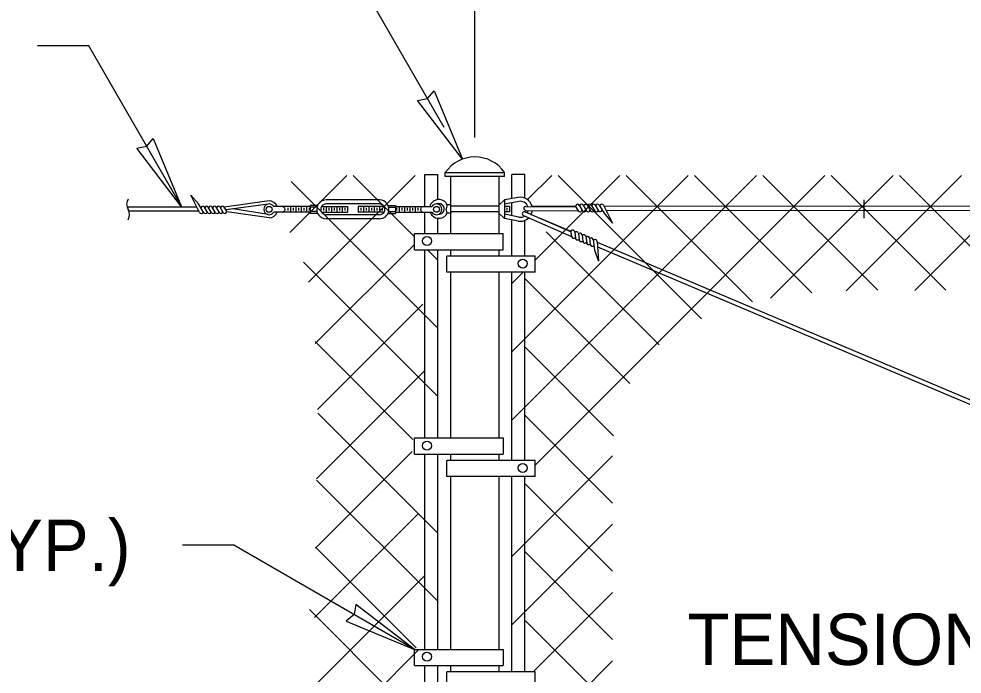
# Model space of a CAD drawing. Extents: x 99862 to 104211, y 98939 to 105076.
# Drawn here: x 100145.4 to 100439.3, y 101445.9 to 101650.2 of the extents above; entities that cross this region are included whole.
import ezdxf

# ---------------------------------------------------------------- set-up
doc = ezdxf.new("R2010")
doc.units = 0
for name, color, linetype in [('Level 15', 7, 'Continuous'), ('Level 2', 7, 'Continuous'), ('Level 20', 7, 'Continuous'), ('Level 4', 7, 'Continuous'), ('Level 7', 7, 'Continuous')]:
    doc.layers.add(name, color=color, linetype=linetype)

msp = doc.modelspace()

# ---------------------------------------------------------------- linework, layer by layer
at = {"layer": 'Level 15'}
for p, q in [((100287.45, 101613.16), (100287.45, 101829.45)), ((100277.92, 101616.32), (100233.56, 101693.15)), ((100167.16, 101641.76), (100151.16, 101641.76)), ((100196.2, 101591.48), (100167.16, 101641.76)), ((100212.4, 101486.13), (100196.4, 101486.13)), ((100268.69, 101453.63), (100212.4, 101486.13))]:
    msp.add_line(p, q, dxfattribs=at)
for points in [[(100283.63, 101606.43), (100269.63, 101624.71), (100272.74, 101625.29), (100274.8, 101627.69)], [(100283.63, 101606.43), (100269.63, 101624.71), (100272.74, 101625.29), (100274.8, 101627.69)], [(100196.11, 101591.62), (100182.11, 101609.9), (100185.23, 101610.48), (100187.28, 101612.89)], [(100196.11, 101591.62), (100182.11, 101609.9), (100185.23, 101610.48), (100187.28, 101612.89)], [(100268.69, 101453.63), (100250.41, 101467.63), (100249.83, 101464.52), (100247.43, 101462.46)]]:
    msp.add_lwpolyline(points, close=True, dxfattribs=at)
at = {"layer": 'Level 2'}
for p, q in [((100201.39, 101592.51), (100198.99, 101595.18)), ((100201.72, 101589.81), (100198.99, 101595.18)), ((100300.99, 101594.5), (100296.67, 101593.73)), ((100203.02, 101589.74), (100201.39, 101592.51)), ((100205.46, 101589.72), (100204.38, 101591.52)), ((100223.34, 101593.42), (100209.37, 101591.43)), ((100223.13, 101592.44), (100209.93, 101590.63)), ((100228.36, 101591.63), (100224.81, 101591.63)), ((100236.13, 101591.63), (100228.36, 101591.63)), ((100230.03, 101591.63), (100230.03, 101589.96)), ((100231.69, 101591.63), (100231.69, 101589.96)), ((100233.36, 101591.63), (100233.36, 101589.96)), ((100235.03, 101591.63), (100235.03, 101589.96)), ((100236.13, 101592.04), (100236.13, 101589.54)), ((100238.49, 101592.04), (100236.13, 101592.04)), ((100239.68, 101591.63), (100247.79, 101591.63)), ((100241.12, 101591.63), (100241.12, 101589.96)), ((100257.79, 101593.71), (100241.13, 101593.71)), ((100257.79, 101592.46), (100241.13, 101592.46)), ((100242.79, 101591.63), (100242.79, 101589.96)), ((100244.45, 101591.63), (100244.45, 101589.96)), ((100246.12, 101591.63), (100246.12, 101589.96)), ((100247.79, 101591.63), (100247.79, 101589.96)), ((100259.22, 101591.63), (100251.12, 101591.63)), ((100251.12, 101591.63), (100251.12, 101589.96)), ((100252.78, 101591.63), (100252.78, 101589.96)), ((100254.45, 101591.63), (100254.45, 101589.96)), ((100256.12, 101591.63), (100256.12, 101589.96)), ((100257.78, 101591.63), (100257.78, 101589.96)), ((100260.42, 101592.04), (100262.79, 101592.04)), ((100262.79, 101592.04), (100262.79, 101589.54)), ((100262.79, 101591.63), (100270.54, 101591.63)), ((100263.88, 101591.63), (100263.88, 101589.96)), ((100265.54, 101591.63), (100265.54, 101589.96)), ((100267.21, 101591.63), (100267.21, 101589.96)), ((100268.88, 101591.63), (100268.88, 101589.96)), ((100270.52, 101591.63), (100274.08, 101591.63)), ((100278.9, 101592.15), (100278.51, 101590.9)), ((100295.03, 101591.73), (100279.88, 101591.73)), ((100296.67, 101593.73), (100294.99, 101592.05)), ((100294.99, 101591.65), (100294.99, 101589.98)), ((100296.67, 101593.73), (100296.67, 101587.89)), ((100301.17, 101593.27), (100296.67, 101592.39)), ((100298.32, 101591.65), (100296.67, 101591.65)), ((100298.32, 101591.65), (100298.32, 101589.98)), ((100303.36, 101591.71), (100318.79, 101591.62)), ((100305.29, 101591.73), (100309.12, 101591.75)), ((100308.63, 101591.74), (100318.86, 101591.79)), ((100320.01, 101592.06), (100321.02, 101590.34)), ((100321.24, 101592.09), (100322.28, 101590.32)), ((100322.48, 101592.12), (100323.54, 101590.35)), ((100323.71, 101592.14), (100324.84, 101590.28)), ((100324.97, 101592.14), (100326.03, 101590.37)), ((100326.24, 101592.12), (100327.93, 101589.26)), ((100327.59, 101592.05), (100330.42, 101586.51)), ((100327.74, 101591.76), (100958.96, 101592.39)), ((100200.87, 101591.48), (100179.1, 101591.48)), ((100201.53, 101590.18), (100179.67, 101590.18)), ((100204.25, 101589.72), (100203.23, 101591.43)), ((100206.66, 101589.74), (100205.64, 101591.45)), ((100207.86, 101589.76), (100206.85, 101591.47)), ((100209.05, 101589.78), (100208.08, 101591.45)), ((100210.02, 101590.5), (100209.37, 101591.43)), ((100223.38, 101588.17), (100210.17, 101590.04)), ((100223.18, 101589.14), (100212.07, 101590.93)), ((100228.36, 101589.96), (100224.81, 101589.96)), ((100236.13, 101589.96), (100228.36, 101589.96)), ((100229.19, 101591.21), (100229.19, 101590.38)), ((100230.86, 101591.21), (100230.86, 101590.38)), ((100232.53, 101591.21), (100232.53, 101590.38)), ((100234.19, 101591.21), (100234.19, 101590.38)), ((100235.86, 101591.21), (100235.86, 101590.38)), ((100238.49, 101589.54), (100236.13, 101589.54)), ((100239.68, 101589.96), (100247.79, 101589.96)), ((100240.29, 101591.21), (100240.29, 101590.38)), ((100257.79, 101589.13), (100241.11, 101589.13)), ((100241.95, 101591.21), (100241.95, 101590.38)), ((100243.62, 101591.21), (100243.62, 101590.38)), ((100245.29, 101591.21), (100245.29, 101590.38)), ((100246.95, 101591.21), (100246.95, 101590.38)), ((100259.22, 101589.96), (100251.12, 101589.96)), ((100251.95, 101591.21), (100251.95, 101590.38)), ((100253.62, 101591.21), (100253.62, 101590.38)), ((100255.28, 101591.21), (100255.28, 101590.38)), ((100256.95, 101591.21), (100256.95, 101590.38)), ((100258.62, 101591.21), (100258.62, 101590.38)), ((100260.42, 101589.54), (100262.79, 101589.54)), ((100262.79, 101589.96), (100270.54, 101589.96)), ((100263.04, 101591.21), (100263.04, 101590.38)), ((100264.71, 101591.21), (100264.71, 101590.38)), ((100266.38, 101591.21), (100266.38, 101590.38)), ((100268.04, 101591.21), (100268.04, 101590.38)), ((100269.71, 101591.21), (100269.71, 101590.38)), ((100270.52, 101589.96), (100274.08, 101589.96)), ((100278.9, 101589.65), (100278.51, 101590.9)), ((100295.01, 101590.06), (100279.96, 101590.06)), ((100294.99, 101590.81), (100294.99, 101589.98)), ((100296.67, 101587.89), (100294.99, 101589.58)), ((100298.32, 101589.98), (100296.67, 101589.98)), ((100301.17, 101588.36), (100296.67, 101589.25)), ((100297.49, 101591.23), (100297.49, 101590.4)), ((100302.64, 101588.83), (100317.62, 101582.34)), ((100303.13, 101589.98), (100317.29, 101583.84)), ((100303.36, 101590.46), (100319.69, 101590.36)), ((100305.03, 101589.19), (100308.44, 101587.75)), ((100319.01, 101591.32), (100319.69, 101590.36)), ((100327.93, 101589.26), (100330.42, 101586.51)), ((100328.4, 101590.46), (100958.31, 101591.09)), ((100257.79, 101587.88), (100241.11, 101587.88)), ((100300.99, 101587.12), (100296.67, 101587.89)), ((100307.99, 101587.94), (100317.41, 101583.98)), ((100317.37, 101583.48), (100317.62, 101582.34)), ((100318.58, 101583.77), (100318.83, 101581.79)), ((100319.73, 101583.31), (100319.99, 101581.28)), ((100320.87, 101582.85), (100321.15, 101580.81)), ((100322.02, 101582.39), (100322.32, 101580.24)), ((100323.17, 101581.89), (100323.46, 101579.85)), ((100324.33, 101581.38), (100324.77, 101578.09)), ((100325.55, 101580.79), (100325.98, 101574.59)), ((100325.56, 101580.53), (100643.48, 101446.13)), ((100324.77, 101578.09), (100325.98, 101574.59)), ((100325.66, 101579.07), (100641.81, 101445.42))]:
    msp.add_line(p, q, dxfattribs=at)
for points in [[(100279.96, 101591.73), (100279.96, 101592.15), (100278.9, 101592.15)], [(100294.99, 101591.65), (100294.99, 101592.05)], [(100238.29, 101591.48), (100236.13, 101591.48)], [(100238.29, 101590.11), (100236.13, 101590.11)], [(100260.62, 101591.48), (100262.79, 101591.48)], [(100260.62, 101590.11), (100262.79, 101590.11)], [(100279.96, 101590.06), (100279.96, 101589.65), (100278.9, 101589.65)], [(100294.99, 101589.98), (100294.99, 101589.58)]]:
    msp.add_lwpolyline(points, dxfattribs=at)
for centre in [(100223.36, 101590.79), (100275.52, 101590.79)]:
    msp.add_circle(centre, 0.916, dxfattribs=at)
for centre, radius, start, end in [((100301.65, 101590.81), 3.75, 13.7093, 100.1113), ((100182.18, 101592.37), 3.2, 150, 210), ((100202.71, 101591.12), 0.605, 30.782, 165.4463), ((100203.91, 101591.14), 0.605, 23.3152, 166.8445), ((100205.12, 101591.14), 0.605, 30.6723, 167.4674), ((100206.35, 101591.15), 0.605, 27.9114, 168.3683), ((100207.56, 101591.15), 0.605, 30.168, 167.2951), ((100208.83, 101591.15), 0.605, 26.9228, 174.8711), ((100223.36, 101590.79), 1.67, 30, 330), ((100223.36, 101590.79), 2.63, 18.6792, 90.4624), ((100227.51, 101590.79), 0.833, 270, 90), ((100241.13, 101590.79), 2.92, 89.9981, 166.4719), ((100241.13, 101590.79), 1.67, 89.9982, 210.0013), ((100257.79, 101590.79), 2.92, 342.3838, 90.0019), ((100257.79, 101590.79), 1.67, 330, 90.0018), ((100271.38, 101590.79), 0.833, 90, 270), ((100276.26, 101590.9), 2.92, 25.3769, 164.6604), ((100275.52, 101590.79), 1.67, 210, 150), ((100276.26, 101590.9), 1.67, 318.0518, 110.808), ((100301.65, 101590.81), 2.5, 21.0207, 101.0207), ((100303.36, 101591.09), 0.625, 90.3003, 270.3003), ((100319.48, 101591.73), 0.625, 28.456, 221.3397), ((100320.73, 101591.74), 0.625, 34.1636, 167.3928), ((100321.98, 101591.74), 0.625, 36.9231, 167.4504), ((100323.23, 101591.75), 0.625, 38.8294, 167.5824), ((100324.48, 101591.76), 0.625, 37.6123, 167.7021), ((100325.73, 101591.76), 0.625, 35.1739, 167.6232), ((100327.03, 101591.77), 0.625, 27.058, 173.8967), ((100176.64, 101589.17), 3.2, 330, 30), ((100202.26, 101590.09), 0.605, 206.9027, 353.7414), ((100203.52, 101590.09), 0.605, 205.8452, 347.468), ((100204.73, 101590.09), 0.605, 204.107, 347.5468), ((100205.94, 101590.09), 0.605, 203.3152, 347.4271), ((100207.15, 101590.1), 0.605, 204.5768, 347.2951), ((100208.36, 101590.1), 0.605, 206.6324, 347.2375), ((100209.57, 101590.1), 0.605, 208.3007, 41.1845), ((100223.36, 101590.79), 2.63, 270.4624, 341.4954), ((100241.13, 101590.79), 2.92, 166.4719, 270), ((100241.13, 101590.79), 1.67, 210.0013, 270), ((100257.79, 101590.79), 2.92, 270, 346.4753), ((100257.79, 101590.79), 1.67, 270, 330), ((100276.26, 101590.9), 2.92, 198.7095, 220.0117), ((100276.26, 101590.9), 2.92, 220.0117, 334.6231), ((100276.26, 101590.9), 1.67, 264.9526, 318.0518), ((100301.65, 101590.81), 2.5, 258.8638, 301.8406), ((100302.88, 101589.41), 0.625, 67.2, 247.2), ((100301.65, 101590.81), 2.5, 332.5747, 351.8513), ((100301.65, 101590.81), 3.75, 333.9004, 354.4593), ((100320.24, 101590.65), 0.625, 207.0781, 355.0264), ((100321.56, 101590.65), 0.625, 210.3232, 347.4504), ((100322.81, 101590.66), 0.625, 208.0667, 348.5236), ((100324.08, 101590.67), 0.625, 210.8276, 347.6226), ((100325.32, 101590.67), 0.625, 218.8294, 346.9998), ((100326.57, 101590.69), 0.625, 210.9373, 345.6016), ((100301.65, 101590.81), 3.75, 259.8887, 314.2398), ((100317.96, 101583.67), 0.625, 5.3557, 198.2394), ((100319.11, 101583.19), 0.625, 11.0633, 144.2925), ((100320.26, 101582.7), 0.625, 13.8228, 144.3501), ((100321.42, 101582.22), 0.625, 15.7291, 144.4821), ((100318.24, 101582.38), 0.625, 183.9778, 331.9261), ((100319.45, 101581.87), 0.625, 187.2229, 324.3501), ((100320.6, 101581.38), 0.625, 184.9664, 325.4233), ((100321.77, 101580.89), 0.625, 187.7273, 324.5224), ((100322.57, 101581.74), 0.625, 14.5121, 144.6018), ((100322.92, 101580.41), 0.625, 195.7291, 323.8995), ((100323.72, 101581.25), 0.625, 12.0736, 144.523), ((100324.08, 101579.94), 0.625, 187.837, 322.5013), ((100324.92, 101580.75), 0.625, 3.9577, 150.7964)]:
    msp.add_arc(centre, radius, start, end, dxfattribs=at)
at = {"layer": 'Level 4'}
for p, q in [((100229.84, 101583.59), (100247.61, 101601.36)), ((100235.6, 101568.08), (100268.89, 101601.36)), ((100268.69, 101582.26), (100249.58, 101601.36)), ((100299.03, 101546.41), (100353.98, 101601.36)), ((100299.03, 101525.12), (100375.26, 101601.36)), ((100303.88, 101593.83), (100311.42, 101601.36)), ((100306.25, 101511.07), (100396.54, 101601.36)), ((100306.3, 101574.97), (100332.7, 101601.36)), ((100358.1, 101556.68), (100313.43, 101601.36)), ((100374.03, 101561.97), (100334.64, 101601.36)), ((100392.45, 101564.82), (100355.91, 101601.36)), ((100413, 101565.55), (100377.19, 101601.36)), ((100379.61, 101563.15), (100417.83, 101601.36)), ((100434.26, 101565.59), (100398.49, 101601.36)), ((100403.15, 101565.41), (100439.1, 101601.36)), ((100454.88, 101566.23), (100419.75, 101601.36)), ((100424.55, 101565.53), (100460.39, 101601.36)), ((100275.96, 101553.71), (100230.2, 101599.47)), ((100408.77, 101588.05), (100408.77, 101593.75)), ((100344.96, 101548.54), (100309.72, 101583.79)), ((100237.75, 101548.93), (100268.69, 101579.87)), ((100275.96, 101574.99), (100272.75, 101578.2)), ((100275.96, 101532.44), (100234.07, 101574.33)), ((100299.03, 101567.69), (100302.51, 101571.18)), ((100335.77, 101536.46), (100303.03, 101569.2)), ((100238.44, 101528.39), (100271.29, 101561.24)), ((100268.19, 101519.03), (100237.69, 101549.56)), ((100330.73, 101520.21), (100302.92, 101548.03)), ((100238.12, 101506.78), (100271.66, 101540.32)), ((100275.96, 101489.86), (100238.54, 101527.28)), ((100330.41, 101499.26), (100302.87, 101526.8)), ((100237.8, 101485.18), (100267.91, 101515.29)), ((100299.03, 101482.57), (100330.41, 101513.94)), ((100276.01, 101468.54), (100238.12, 101506.43)), ((100330.41, 101477.99), (100303.09, 101505.3)), ((100237.48, 101463.57), (100269.94, 101496.03)), ((100299.13, 101461.39), (100330.41, 101492.67)), ((100269.16, 101454.11), (100237.81, 101485.46)), ((100330.41, 101456.73), (100303.07, 101484.1)), ((100236.47, 101441.29), (100271.77, 101476.59)), ((100305.96, 101446.96), (100330.41, 101471.4)), ((100275.96, 101426.04), (100235.97, 101466.03)), ((100330.41, 101435.42), (100303.25, 101462.57)), ((100236.84, 101420.38), (100269.94, 101453.48)), ((100299.03, 101418.73), (100330.41, 101450.1))]:
    msp.add_line(p, q, dxfattribs=at)
at = {"layer": 'Level 7'}
for p, q in [((100271.94, 101592.37), (100271.94, 101601.64)), ((100271.94, 101601.64), (100275.96, 101601.64)), ((100275.96, 101593.8), (100275.96, 101601.64)), ((100278.27, 101602.27), (100296.72, 101602.27)), ((100278.27, 101601.02), (100278.27, 101602.27)), ((100296.72, 101601.02), (100278.27, 101601.02)), ((100279.97, 101583.21), (100279.97, 101601.02)), ((100295.02, 101583.21), (100295.02, 101601.02)), ((100296.72, 101601.02), (100296.72, 101602.27)), ((100299.03, 101594.15), (100299.03, 101601.64)), ((100303.05, 101601.64), (100299.03, 101601.64)), ((100303.05, 101594.29), (100303.05, 101601.64)), ((100271.94, 101591.63), (100271.94, 101592.37)), ((100299.03, 101588.78), (100299.03, 101592.85)), ((100271.94, 101583.21), (100271.94, 101589.96)), ((100275.96, 101583.21), (100275.96, 101588)), ((100299.03, 101576.19), (100299.03, 101587.47)), ((100303.05, 101576.19), (100303.05, 101587.34)), ((100268.69, 101583.21), (100296.27, 101583.21)), ((100268.69, 101578.2), (100268.69, 101583.21)), ((100296.27, 101578.2), (100296.27, 101583.21)), ((100268.69, 101578.2), (100296.27, 101578.2)), ((100271.94, 101519.53), (100271.94, 101578.2)), ((100275.96, 101519.53), (100275.96, 101578.2)), ((100279.97, 101576.19), (100279.97, 101578.2)), ((100295.02, 101576.19), (100295.02, 101578.2)), ((100306.3, 101576.19), (100278.72, 101576.19)), ((100278.72, 101571.18), (100278.72, 101576.19)), ((100306.3, 101571.18), (100306.3, 101576.19)), ((100306.3, 101571.18), (100278.72, 101571.18)), ((100279.97, 101519.53), (100279.97, 101571.18)), ((100295.02, 101519.53), (100295.02, 101571.18)), ((100299.03, 101512.51), (100299.03, 101571.18)), ((100303.05, 101512.51), (100303.05, 101571.18)), ((100268.69, 101519.53), (100296.27, 101519.53)), ((100268.69, 101514.52), (100268.69, 101519.53)), ((100296.27, 101519.53), (100296.27, 101514.52)), ((100268.69, 101514.52), (100296.27, 101514.52)), ((100271.94, 101453.63), (100271.94, 101514.52)), ((100275.96, 101453.63), (100275.96, 101514.52)), ((100306.3, 101512.51), (100278.72, 101512.51)), ((100278.72, 101507.5), (100278.72, 101512.51)), ((100279.97, 101512.51), (100279.97, 101514.52)), ((100295.02, 101512.51), (100295.02, 101514.52)), ((100306.3, 101507.5), (100306.3, 101512.51)), ((100306.3, 101507.5), (100278.72, 101507.5)), ((100279.97, 101453.63), (100279.97, 101507.5)), ((100295.02, 101453.63), (100295.02, 101507.5)), ((100299.03, 101446.61), (100299.03, 101507.5)), ((100303.05, 101446.61), (100303.05, 101507.5)), ((100268.69, 101453.63), (100296.27, 101453.63)), ((100268.69, 101448.61), (100268.69, 101453.63)), ((100296.27, 101453.63), (100296.27, 101448.61)), ((100268.69, 101448.61), (100296.27, 101448.61)), ((100271.94, 101390.33), (100271.94, 101448.61)), ((100275.96, 101390.33), (100275.96, 101448.61)), ((100279.97, 101446.61), (100279.97, 101448.61)), ((100295.02, 101446.61), (100295.02, 101448.61)), ((100306.3, 101446.61), (100278.72, 101446.61)), ((100278.72, 101441.6), (100278.72, 101446.61)), ((100306.3, 101441.6), (100306.3, 101446.61))]:
    msp.add_line(p, q, dxfattribs=at)
for centre in [(100272.58, 101580.91), (100302.41, 101573.9), (100272.58, 101517.13), (100302.41, 101510.21), (100272.58, 101451.38)]:
    msp.add_circle(centre, 1.41, dxfattribs=at)
msp.add_arc((100287.5, 101595.92), 11.2, 34.5285, 145.4715, dxfattribs=at)

# ---------------------------------------------------------------- texts
at = {"layer": 'Level 20'}
msp.add_text('FABRIC BAND (TYP.)', height=16, rotation=360, dxfattribs=at).set_placement((99968.63, 101478.08))
msp.add_text('TENSION', height=16, dxfattribs=at).set_placement((100353.75, 101448.79))

doc.saveas('drawing.dxf')
